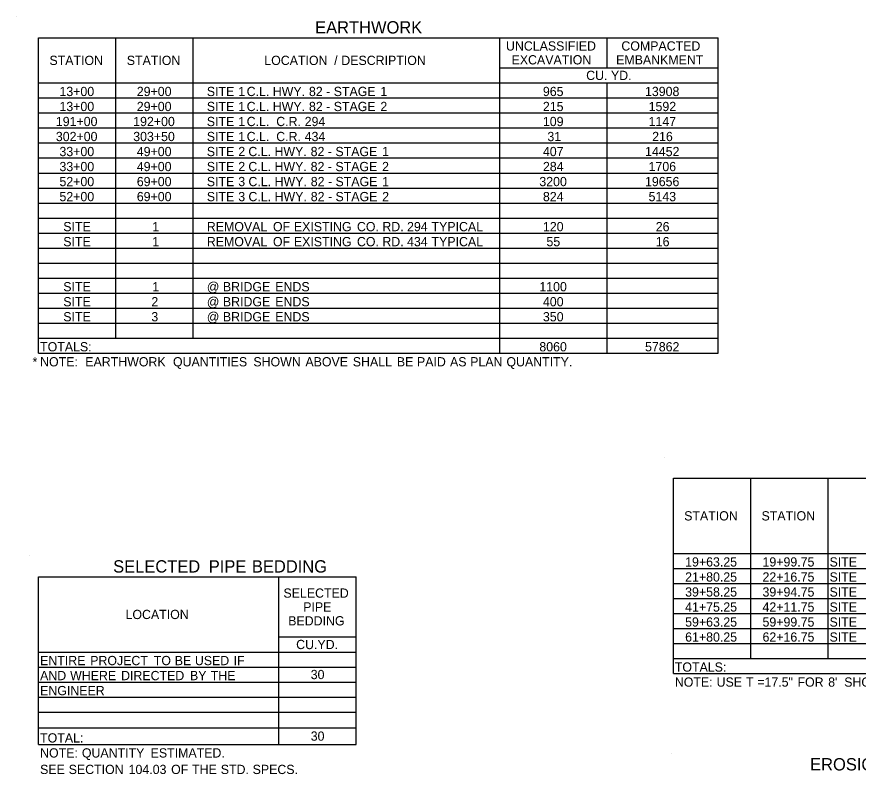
# Model space of a CAD drawing. Extents: x 977434 to 989596, y 1525697 to 1528336.
# Drawn here: x 980847 to 981393, y 1527844 to 1528336 of the extents above; entities that cross this region are included whole.
import ezdxf

# ---------------------------------------------------------------- set-up
doc = ezdxf.new("R2010")
doc.units = 0
doc.layers.add('Default', color=7, linetype='Continuous')
doc.layers.add('R_Border Prem', color=7, linetype='Continuous')

msp = doc.modelspace()

# ---------------------------------------------------------------- linework, layer by layer
at = {"layer": 'Default'}
for p, q in [((980860.84, 1528322.03), (981302.03, 1528322.03)), ((980860.84, 1528117.28), (980860.84, 1528322.03)), ((980860.84, 1528117.28), (980860.84, 1528322.03)), ((980911.05, 1528127.03), (980911.05, 1528322.03)), ((980961.26, 1528127.03), (980961.26, 1528322.03)), ((981160.16, 1528117.28), (981160.16, 1528322.03)), ((981229.88, 1528302.53), (981229.88, 1528322.03)), ((981302.03, 1528117.28), (981302.03, 1528322.03)), ((981302.03, 1528117.28), (981302.03, 1528322.03)), ((981160.16, 1528302.53), (981302.03, 1528302.53)), ((980860.84, 1528292.78), (981302.03, 1528292.78)), ((980911.05, 1528127.03), (980911.05, 1528292.78)), ((980961.26, 1528185.53), (980961.26, 1528292.78)), ((981160.16, 1528214.78), (981160.16, 1528292.78)), ((981229.88, 1528117.28), (981229.88, 1528292.78)), ((980860.84, 1528283.03), (981302.03, 1528283.03)), ((980860.84, 1528273.28), (981302.03, 1528273.28)), ((980860.84, 1528263.53), (981302.03, 1528263.53)), ((980860.84, 1528253.78), (981302.03, 1528253.78)), ((980860.84, 1528244.03), (981302.03, 1528244.03)), ((980860.84, 1528234.28), (981302.03, 1528234.28)), ((980860.84, 1528224.53), (981302.03, 1528224.53)), ((980860.84, 1528214.78), (981302.03, 1528214.78)), ((980860.84, 1528205.03), (981302.03, 1528205.03)), ((980860.84, 1528195.28), (981302.03, 1528195.28)), ((980860.84, 1528185.53), (981302.03, 1528185.53)), ((980860.84, 1528175.78), (981302.03, 1528175.78)), ((980860.84, 1528166.03), (981302.03, 1528166.03)), ((980860.84, 1528156.28), (981302.03, 1528156.28)), ((980860.84, 1528146.53), (981302.03, 1528146.53)), ((980860.84, 1528136.78), (981302.03, 1528136.78)), ((980961.26, 1528127.03), (980961.26, 1528136.78)), ((981160.16, 1528127.03), (981160.16, 1528136.78)), ((980860.84, 1528127.03), (981302.03, 1528127.03)), ((980860.84, 1528127.03), (981302.03, 1528127.03)), ((980860.84, 1528117.28), (981302.03, 1528117.28)), ((981272.88, 1528036.08), (981837.89, 1528036.08)), ((981272.88, 1527909.33), (981272.88, 1528036.08)), ((981272.88, 1527909.33), (981272.88, 1528036.08)), ((981323.09, 1527919.08), (981323.09, 1528036.08)), ((981373.31, 1527919.08), (981373.31, 1528036.08)), ((981272.88, 1527987.33), (981837.89, 1527987.33)), ((981323.09, 1527919.08), (981323.09, 1527987.33)), ((981373.31, 1527919.08), (981373.31, 1527987.33)), ((981272.88, 1527977.58), (981837.89, 1527977.58)), ((980860.84, 1527972.05), (981067.05, 1527972.05)), ((980860.84, 1527863.34), (980860.84, 1527972.05)), ((980860.84, 1527863.34), (980860.84, 1527972.05)), ((981016.84, 1527863.34), (981016.84, 1527972.05)), ((981067.05, 1527863.34), (981067.05, 1527972.05)), ((981067.05, 1527863.34), (981067.05, 1527972.05)), ((981272.88, 1527967.83), (981837.89, 1527967.83)), ((981272.88, 1527958.08), (981837.89, 1527958.08)), ((981272.88, 1527948.33), (981837.89, 1527948.33)), ((981272.88, 1527938.58), (981837.89, 1527938.58)), ((981016.84, 1527933.05), (981067.05, 1527933.05)), ((981272.88, 1527928.83), (981837.89, 1527928.83)), ((980860.84, 1527923.3), (981067.05, 1527923.3)), ((981016.84, 1527863.34), (981016.84, 1527923.3)), ((981272.88, 1527919.08), (981837.89, 1527919.08)), ((980860.84, 1527913.55), (981067.05, 1527913.55)), ((981272.88, 1527909.33), (981837.89, 1527909.33)), ((980860.84, 1527903.8), (981067.05, 1527903.8)), ((980860.84, 1527894.05), (981067.05, 1527894.05)), ((980860.84, 1527884.3), (981067.05, 1527884.3)), ((980860.84, 1527874.07), (981067.05, 1527874.07)), ((980860.84, 1527863.34), (981067.05, 1527863.34))]:
    msp.add_line(p, q, dxfattribs=at)
at = {"layer": 'R_Border Prem'}
for p, q in [((980846.7, 1528335.68), (980846.7, 1528335.68)), ((981267.03, 1528049.73), (981267.03, 1528049.73)), ((980854.99, 1527985.7), (980854.99, 1527985.7)), ((981271.59, 1527857.22), (981271.59, 1527857.22))]:
    msp.add_line(p, q, dxfattribs=at)

# ---------------------------------------------------------------- texts
at = {"layer": 'Default'}
for s, height, p in [('EARTHWORK', 8, (981040.35, 1528324.86)), ('UNCLASSIFIED', 6, (981164.25, 1528313.78)), ('COMPACTED', 6, (981239.14, 1528313.78)), ('STATION', 6, (980867.88, 1528304.41)), ('STATION', 6, (980918.09, 1528304.41)), ('LOCATION', 6, (981007.35, 1528304.41)), (' /', 6, (981050.46, 1528304.41)), (' DESCRIPTION', 6, (981055.12, 1528304.41)), ('EXCAVATION', 6, (981167.87, 1528304.78)), ('EMBANKMENT', 6, (981235.76, 1528304.78)), ('CU.', 6, (981216.3, 1528294.66)), (' YD.', 6, (981230.16, 1528294.66)), ('13+00', 6, (980874.38, 1528284.23)), ('29+00', 6, (980924.59, 1528284.23)), ('SITE', 6, (980970.04, 1528284.23)), (' 1', 6, (980988.23, 1528284.23)), (' C.L.', 6, (980993.67, 1528284.23)), (' HWY.', 6, (981010.64, 1528284.23)), (' 82', 6, (981034.12, 1528284.23)), (' STAGE', 6, (981050.18, 1528284.23)), (' 1', 6, (981080.48, 1528284.23)), ('965', 6, (981188.2, 1528284.23)), ('13908', 6, (981254.49, 1528284.23)), (' -', 6, (981045.33, 1528284.23)), ('13+00', 6, (980874.38, 1528274.48)), ('29+00', 6, (980924.59, 1528274.48)), ('SITE', 6, (980970.04, 1528274.48)), (' 1', 6, (980988.23, 1528274.48)), (' C.L.', 6, (980993.67, 1528274.48)), (' HWY.', 6, (981010.64, 1528274.48)), (' 82', 6, (981034.12, 1528274.48)), (' STAGE', 6, (981050.18, 1528274.48)), (' 2', 6, (981080.48, 1528274.48)), ('215', 6, (981188.2, 1528274.48)), ('1592', 6, (981256.85, 1528274.48)), (' -', 6, (981045.33, 1528274.48)), ('191+00', 6, (980872.05, 1528264.73)), ('192+00', 6, (980922.26, 1528264.73)), ('SITE', 6, (980970.04, 1528264.73)), (' 1', 6, (980988.23, 1528264.73)), (' C.L.', 6, (980993.67, 1528264.73)), ('  C.R.', 6, (981010.64, 1528264.73)), (' 294', 6, (981031.33, 1528264.73)), ('109', 6, (981188.21, 1528264.73)), ('1147', 6, (981256.82, 1528264.73)), ('302+00', 6, (980872.05, 1528254.98)), ('303+50', 6, (980922.26, 1528254.98)), ('SITE', 6, (980970.04, 1528254.98)), (' 1', 6, (980988.23, 1528254.98)), (' C.L.', 6, (980993.67, 1528254.98)), ('  C.R.', 6, (981010.64, 1528254.98)), (' 434', 6, (981031.33, 1528254.98)), ('31', 6, (981191.13, 1528254.98)), ('216', 6, (981259.15, 1528254.98)), ('33+00', 6, (980874.38, 1528245.23)), ('49+00', 6, (980924.59, 1528245.23)), ('SITE', 6, (980970.04, 1528245.23)), (' 2', 6, (980988.23, 1528245.23)), (' C.L.', 6, (980994.77, 1528245.23)), (' HWY.', 6, (981011.74, 1528245.23)), (' 82', 6, (981035.22, 1528245.23)), (' STAGE', 6, (981051.28, 1528245.23)), (' 1', 6, (981081.58, 1528245.23)), ('407', 6, (981188.22, 1528245.23)), ('14452', 6, (981254.52, 1528245.23)), (' -', 6, (981046.42, 1528245.23)), ('33+00', 6, (980874.38, 1528235.48)), ('49+00', 6, (980924.59, 1528235.48)), ('SITE', 6, (980970.04, 1528235.48)), (' 2', 6, (980988.23, 1528235.48)), (' C.L.', 6, (980994.77, 1528235.48)), (' HWY.', 6, (981011.74, 1528235.48)), (' 82', 6, (981035.22, 1528235.48)), (' STAGE', 6, (981051.28, 1528235.48)), (' 2', 6, (981081.58, 1528235.48)), ('284', 6, (981188.23, 1528235.48)), ('1706', 6, (981256.82, 1528235.48)), (' -', 6, (981046.42, 1528235.48)), ('52+00', 6, (980874.38, 1528225.73)), ('69+00', 6, (980924.59, 1528225.73)), ('SITE', 6, (980970.04, 1528225.73)), (' 3', 6, (980988.23, 1528225.73)), (' C.L.', 6, (980994.83, 1528225.73)), (' HWY.', 6, (981011.8, 1528225.73)), (' 82', 6, (981035.28, 1528225.73)), (' STAGE', 6, (981051.34, 1528225.73)), (' 1', 6, (981081.65, 1528225.73)), ('3200', 6, (981185.9, 1528225.73)), ('19656', 6, (981254.49, 1528225.73)), (' -', 6, (981046.49, 1528225.73)), ('52+00', 6, (980874.38, 1528215.98)), ('69+00', 6, (980924.59, 1528215.98)), ('SITE', 6, (980970.04, 1528215.98)), (' 3', 6, (980988.23, 1528215.98)), (' C.L.', 6, (980994.83, 1528215.98)), (' HWY.', 6, (981011.8, 1528215.98)), (' 82', 6, (981035.28, 1528215.98)), (' -', 6, (981046.49, 1528215.98)), (' STAGE', 6, (981051.34, 1528215.98)), (' 2', 6, (981081.65, 1528215.98)), ('824', 6, (981188.23, 1528215.98)), ('5143', 6, (981256.82, 1528215.98)), ('SITE', 6, (980876.85, 1528196.48)), ('1', 6, (980934.6, 1528196.48)), ('REMOVAL', 6, (980970.04, 1528196.48)), (' OF', 6, (981010.74, 1528196.48)), (' EXISTING', 6, (981024.33, 1528196.48)), (' CO.', 6, (981065.26, 1528196.48)), (' RD.', 6, (981081.76, 1528196.48)), (' 294', 6, (981097.79, 1528196.48)), (' TYPICAL', 6, (981113.69, 1528196.48)), ('120', 6, (981188.23, 1528196.48)), ('26', 6, (981261.48, 1528196.48)), ('SITE', 6, (980876.85, 1528186.73)), ('1', 6, (980934.6, 1528186.73)), ('REMOVAL', 6, (980970.04, 1528186.73)), (' OF', 6, (981010.74, 1528186.73)), (' EXISTING', 6, (981024.33, 1528186.73)), (' CO.', 6, (981065.26, 1528186.73)), (' RD.', 6, (981081.76, 1528186.73)), (' 434', 6, (981097.79, 1528186.73)), (' TYPICAL', 6, (981113.69, 1528186.73)), ('55', 6, (981190.53, 1528186.73)), ('16', 6, (981261.48, 1528186.73)), ('@', 6, (980970.04, 1528157.48)), ('SITE', 6, (980876.85, 1528157.48)), ('1', 6, (980934.6, 1528157.48)), (' BRIDGE', 6, (980978.25, 1528157.48)), (' ENDS', 6, (981012.27, 1528157.48)), ('1100', 6, (981185.9, 1528157.48)), ('SITE', 6, (980876.85, 1528147.73)), ('2', 6, (980934.05, 1528147.73)), ('@', 6, (980970.04, 1528147.73)), (' BRIDGE', 6, (980978.25, 1528147.73)), (' ENDS', 6, (981012.27, 1528147.73)), ('400', 6, (981188.23, 1528147.73)), ('SITE', 6, (980876.85, 1528137.98)), ('3', 6, (980934.02, 1528137.98)), ('@', 6, (980970.04, 1528137.98)), (' BRIDGE', 6, (980978.25, 1528137.98)), (' ENDS', 6, (981012.27, 1528137.98)), ('350', 6, (981188.23, 1528137.98)), ('TOTALS:', 6, (980861.81, 1528118.48)), ('8060', 6, (981185.9, 1528118.48)), ('57862', 6, (981254.51, 1528118.48)), ('*', 6, (980856.89, 1528108.73)), ('NOTE:', 6, (980861.81, 1528108.73)), ('  EARTHWORK', 6, (980886.7, 1528108.73)), (' QUANTITIES', 6, (980945.84, 1528108.73)), (' SHOWN', 6, (980998.03, 1528108.73)), (' ABOVE', 6, (981031.81, 1528108.73)), (' SHALL', 6, (981062.58, 1528108.73)), (' BE', 6, (981091.18, 1528108.73)), (' PAID', 6, (981104.24, 1528108.73)), (' AS', 6, (981125.69, 1528108.73)), (' PLAN', 6, (981138.76, 1528108.73)), (' QUANTITY.', 6, (981162.31, 1528108.73)), ('STATION', 6, (981279.93, 1528008.7)), ('STATION', 6, (981330.14, 1528008.7)), ('19+63.25', 6, (981280.56, 1527978.78)), ('19+99.75', 6, (981330.78, 1527978.78)), ('SITE', 6, (981374.28, 1527978.78)), ('SELECTED', 8, (980909.25, 1527974.88)), (' PIPE', 8, (980968.33, 1527974.88)), (' BEDDING', 8, (980996.35, 1527974.88)), ('21+80.25', 6, (981280.56, 1527969.03)), ('22+16.75', 6, (981330.78, 1527969.03)), ('SITE', 6, (981374.28, 1527969.03)), ('SELECTED', 6, (981019.79, 1527958.55)), ('39+58.25', 6, (981280.56, 1527959.28)), ('39+94.75', 6, (981330.78, 1527959.28)), ('SITE', 6, (981374.28, 1527959.28)), ('LOCATION', 6, (980917.28, 1527944.68)), ('PIPE', 6, (981032.6, 1527949.55)), ('41+75.25', 6, (981280.56, 1527949.53)), ('42+11.75', 6, (981330.78, 1527949.53)), ('SITE', 6, (981374.28, 1527949.53)), ('BEDDING', 6, (981022.87, 1527940.55)), ('59+63.25', 6, (981280.56, 1527939.78)), ('59+99.75', 6, (981330.78, 1527939.78)), ('SITE', 6, (981374.28, 1527939.78)), ('61+80.25', 6, (981280.56, 1527930.03)), ('62+16.75', 6, (981330.78, 1527930.03)), ('SITE', 6, (981374.28, 1527930.03)), ('CU.YD.', 6, (981028.03, 1527925.18)), ('ENTIRE', 6, (980861.81, 1527914.75)), (' PROJECT', 6, (980892.11, 1527914.75)), (' TO', 6, (980933.4, 1527914.75)), (' BE', 6, (980947, 1527914.75)), (' USED', 6, (980960.06, 1527914.75)), (' IF', 6, (980985.24, 1527914.75)), ('TOTALS:', 6, (981273.86, 1527910.53)), ('AND', 6, (980861.81, 1527905)), (' WHERE', 6, (980879.07, 1527905)), (' DIRECTED', 6, (980912.15, 1527905)), (' BY', 6, (980956.89, 1527905)), (' THE', 6, (980970.34, 1527905)), ('30', 6, (981037.49, 1527905.68)), ('NOTE:', 6, (981273.86, 1527900.78)), (' USE', 6, (981298.74, 1527900.78)), (' T', 6, (981317.86, 1527900.78)), (' =17.5"', 6, (981325.14, 1527900.78)), (' FOR', 6, (981351.26, 1527900.78)), (" 8'", 6, (981371.17, 1527900.78)), ('  SHOULDER.', 6, (981379.36, 1527900.78)), ('ENGINEER', 6, (980861.81, 1527895.25)), ('TOTAL:', 6, (980861.81, 1527864.54)), ('30', 6, (981037.49, 1527865.7)), ('NOTE:', 6, (980861.81, 1527854.79)), (' QUANTITY', 6, (980886.7, 1527854.79)), (' ESTIMATED.', 6, (980931.35, 1527854.79)), ('EROSION', 8, (981361.68, 1527846.4)), ('SEE', 6, (980861.81, 1527844.07)), (' SECTION', 6, (980878.14, 1527844.07)), (' 104.03', 6, (980917.05, 1527844.07)), (' OF', 6, (980944.63, 1527844.07)), (' THE', 6, (980958.22, 1527844.07)), (' STD.', 6, (980976.86, 1527844.07)), (' SPECS.', 6, (980997.56, 1527844.07))]:
    msp.add_text(s, height=height, dxfattribs=at).set_placement(p)

doc.saveas('drawing.dxf')
